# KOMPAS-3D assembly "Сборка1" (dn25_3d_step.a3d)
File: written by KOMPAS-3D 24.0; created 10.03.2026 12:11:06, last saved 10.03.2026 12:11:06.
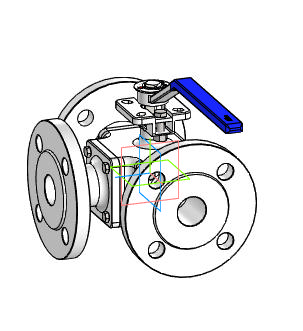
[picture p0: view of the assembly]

Document properties: Автор: R2D2; Полное имя файла: E:\Работа\Зайцев\BV3232P(4pc)-FP-3WL-F-ISO-H Кран шаровой DN.ru Ду15-100 Ру16\DN25\исходные материалы\dn25_3d_step.a3d

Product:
- Component [detail]: Деталь  | qty 1  | Автор: R2D2; source file: Деталь Деталь.m3d
- Component [detail]: Деталь1  | qty 1  | Автор: R2D2; source file: Деталь1 Деталь1.m3d
- Component [detail]: AS 1110 - M6 x 20  | qty 1  | Автор: R2D2; source file: AS 1110 - M6 x 20 AS 1110 - M6 x 20.m3d
- Component [detail]: AS 1110 - M6 x 20  | qty 1  | Комментарий: Болты и винты   шестигранные точные   метрические ISO; Автор: R2D2; additional columns: Сталь, мягкая; source file: AS 1110 - M6 x 20 AS 1110 - M6 x 20.m3d
- Component [detail]: ANSI B18.2.4.2M - M6x1 - 10  | designation ANSI B18.2.4.2M - M6x1  | qty 1  | Автор: R2D2; source file: ANSI B18.2.4.2M - M6x1 ANSI B18.2.4.2M - M6x1 - 10.m3d
- Component [detail]: ANSI B18.2.4.2M - M6x1 - 10  | designation ANSI B18.2.4.2M - M6x1  | qty 1  | Комментарий: Типы метрических   шестигранных гаек   2; Автор: R2D2; additional columns: Сталь, мягкая; source file: ANSI B18.2.4.2M - M6x1 ANSI B18.2.4.2M - M6x1 - 10.m3d
- Component [detail]: AS 1110 - M5 x 10  | qty 1  | Автор: R2D2; source file: AS 1110 - M5 x 10 AS 1110 - M5 x 10.m3d
- Component [detail]: AS 1110 - M5 x 10  | qty 11  | Комментарий: Болты и винты   шестигранные точные   метрические ISO; Автор: R2D2; additional columns: Сталь, мягкая; source file: AS 1110 - M5 x 10 AS 1110 - M5 x 10.m3d
- Part/product: Сборка1

Referenced files in E:\Работа\Зайцев\BV3232P(4pc)-FP-3WL-F-ISO-H Кран шаровой DN.ru Ду15-100 Ру16\DN25\исходные материалы\: Деталь Деталь.m3d, Деталь1 Деталь1.m3d, AS 1110 - M6 x 20 AS 1110 - M6 x 20.m3d, ANSI B18.2.4.2M - M6x1 ANSI B18.2.4.2M - M6x1 - 10.m3d, AS 1110 - M5 x 10 AS 1110 - M5 x 10.m3d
